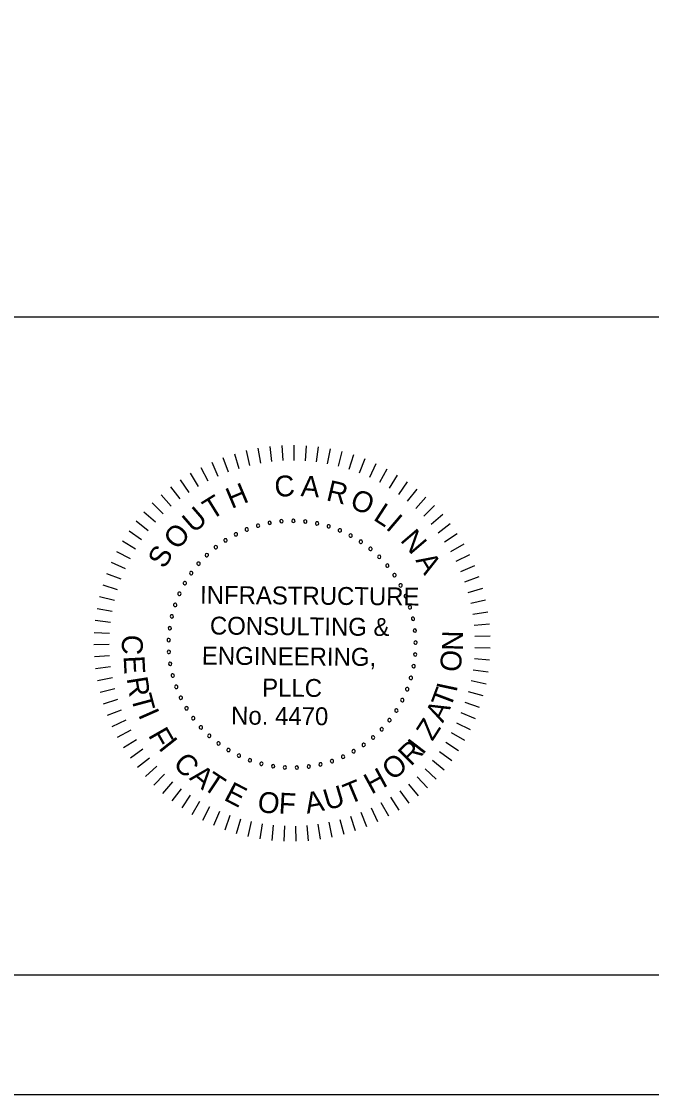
# Model space of a CAD drawing. Extents: x -144.4 to -96.3, y -117.1 to -87.8.
# Drawn here: x -110.83 to -107.33, y -117.06 to -111.1 of the extents above; entities that cross this region are included whole.
import ezdxf

# ---------------------------------------------------------------- set-up
doc = ezdxf.new("R2010")
doc.units = 0
for name, color, linetype in [('BR_BORDER LINES', 7, 'Continuous'), ('BR_TEXT', 7, 'Continuous'), ('Level 31', 7, 'Continuous')]:
    doc.layers.add(name, color=color, linetype=linetype)

msp = doc.modelspace()

# ---------------------------------------------------------------- linework, layer by layer
at = {"layer": 'BR_BORDER LINES'}
for p, q in [((-114.2473, -112.7399), (-107.1116, -112.7399)), ((-141.9121, -116.3976), (-97.1362, -116.3976))]:
    msp.add_line(p, q, dxfattribs=at)
at = {"layer": 'BR_TEXT'}
for p, q in [((-109.5838, -113.4838), (-109.564, -113.5661)), ((-109.518, -113.4702), (-109.5033, -113.5536)), ((-109.4516, -113.4606), (-109.442, -113.5448)), ((-109.3847, -113.4551), (-109.3802, -113.5397)), ((-109.3175, -113.4537), (-109.3182, -113.5384)), ((-109.2505, -113.4564), (-109.2563, -113.5409)), ((-109.1836, -113.4632), (-109.1946, -113.5471)), ((-109.1174, -113.474), (-109.1335, -113.5571)), ((-109.7122, -113.5229), (-109.6825, -113.6022)), ((-109.6486, -113.5014), (-109.6238, -113.5824)), ((-109.0519, -113.4888), (-109.073, -113.5708)), ((-108.9875, -113.5077), (-109.0135, -113.5882)), ((-108.9243, -113.5304), (-108.9552, -113.6092)), ((-109.8349, -113.5773), (-109.7958, -113.6524)), ((-109.7744, -113.5482), (-109.7399, -113.6256)), ((-108.8626, -113.5569), (-108.8983, -113.6337)), ((-108.8026, -113.5871), (-108.8429, -113.6616)), ((-109.9501, -113.6463), (-109.9021, -113.7161)), ((-109.8935, -113.61), (-109.8499, -113.6826)), ((-108.7446, -113.6209), (-108.7894, -113.6928)), ((-108.6888, -113.6582), (-108.7379, -113.7272)), ((-110.0043, -113.6859), (-109.9522, -113.7527)), ((-108.6353, -113.6989), (-108.6885, -113.7648)), ((-110.1049, -113.7747), (-110.0451, -113.8346)), ((-110.056, -113.7287), (-109.9999, -113.7922)), ((-108.5845, -113.7427), (-108.6416, -113.8052)), ((-110.151, -113.8235), (-110.0877, -113.8796)), ((-108.5364, -113.7895), (-108.5972, -113.8484)), ((-108.4912, -113.8392), (-108.5555, -113.8943)), ((-110.1941, -113.875), (-110.1274, -113.9272)), ((-108.4491, -113.8916), (-108.5167, -113.9426)), ((-110.2339, -113.9291), (-110.1642, -113.9771)), ((-108.4104, -113.9464), (-108.4809, -113.9932)), ((-110.2703, -113.9855), (-110.1978, -114.0292)), ((-108.375, -114.0034), (-108.4482, -114.0459)), ((-110.3033, -114.044), (-110.2282, -114.0832)), ((-108.3432, -114.0626), (-108.4189, -114.1005)), ((-110.3326, -114.1044), (-110.2553, -114.1389)), ((-108.315, -114.1235), (-108.3929, -114.1568)), ((-110.3582, -114.1665), (-110.2789, -114.1962)), ((-108.2906, -114.1861), (-108.3704, -114.2145)), ((-110.3799, -114.23), (-110.299, -114.2549)), ((-108.2701, -114.25), (-108.3514, -114.2735)), ((-110.3977, -114.2947), (-110.3154, -114.3146)), ((-108.2535, -114.3151), (-108.3361, -114.3336)), ((-110.4116, -114.3604), (-110.3282, -114.3753)), ((-108.2409, -114.381), (-108.3245, -114.3945)), ((-110.4214, -114.4269), (-110.3373, -114.4366)), ((-110.4271, -114.4938), (-110.3426, -114.4983)), ((-108.2323, -114.4476), (-108.3166, -114.4559)), ((-110.4288, -114.5609), (-110.3441, -114.5603)), ((-108.2279, -114.5146), (-108.3125, -114.5178)), ((-108.2275, -114.5817), (-108.3121, -114.5798)), ((-110.4264, -114.628), (-110.3419, -114.6222)), ((-108.2312, -114.6488), (-108.3155, -114.6416)), ((-110.4199, -114.6948), (-110.3359, -114.6839)), ((-108.239, -114.7155), (-108.3227, -114.7032)), ((-110.4093, -114.7611), (-110.3261, -114.7451)), ((-108.2508, -114.7816), (-108.3337, -114.7642)), ((-110.3947, -114.8266), (-110.3126, -114.8056)), ((-108.2666, -114.8468), (-108.3483, -114.8244)), ((-110.3761, -114.8912), (-110.2955, -114.8652)), ((-108.2864, -114.911), (-108.3666, -114.8836)), ((-110.3536, -114.9544), (-110.2748, -114.9236)), ((-108.3101, -114.9738), (-108.3884, -114.9416)), ((-110.3273, -115.0162), (-110.2505, -114.9806)), ((-110.2973, -115.0763), (-110.2228, -115.0361)), ((-108.3376, -115.0351), (-108.4138, -114.9982)), ((-110.2637, -115.1344), (-110.1918, -115.0897)), ((-108.3687, -115.0946), (-108.4425, -115.0531)), ((-110.2266, -115.1904), (-110.1576, -115.1414)), ((-108.4415, -115.2073), (-108.5098, -115.1572)), ((-108.4034, -115.152), (-108.4746, -115.1062)), ((-110.1862, -115.244), (-110.1202, -115.1909)), ((-108.483, -115.2601), (-108.5481, -115.2059)), ((-110.1426, -115.295), (-110.08, -115.238)), ((-108.5276, -115.3103), (-108.5892, -115.2523)), ((-110.0959, -115.3433), (-110.0369, -115.2825)), ((-110.0464, -115.3886), (-109.9912, -115.3244)), ((-108.5751, -115.3577), (-108.6331, -115.296)), ((-109.9942, -115.4309), (-109.943, -115.3634)), ((-108.6785, -115.4434), (-108.7285, -115.3751)), ((-108.6255, -115.4021), (-108.6796, -115.337)), ((-109.9395, -115.4699), (-109.8926, -115.3994)), ((-109.8826, -115.5055), (-109.84, -115.4323)), ((-108.7915, -115.5158), (-108.8329, -115.4419)), ((-108.7339, -115.4813), (-108.7797, -115.4101)), ((-109.8236, -115.5375), (-109.7856, -115.4618)), ((-109.7627, -115.5659), (-109.7294, -115.488)), ((-109.7003, -115.5905), (-109.6717, -115.5108)), ((-108.9125, -115.5739), (-108.9445, -115.4956)), ((-108.8511, -115.5467), (-108.8879, -115.4704)), ((-109.6364, -115.6113), (-109.6128, -115.53)), ((-109.5714, -115.6281), (-109.5528, -115.5455)), ((-109.5055, -115.641), (-109.492, -115.5574)), ((-109.439, -115.6498), (-109.4305, -115.5655)), ((-109.372, -115.6545), (-109.3687, -115.5699)), ((-109.3048, -115.6551), (-109.3067, -115.5705)), ((-109.2378, -115.6517), (-109.2448, -115.5673)), ((-109.1711, -115.6441), (-109.1832, -115.5603)), ((-109.1049, -115.6325), (-109.1222, -115.5496)), ((-109.0396, -115.6169), (-109.0619, -115.5352)), ((-108.9754, -115.5974), (-109.0026, -115.5172))]:
    msp.add_line(p, q, dxfattribs=at)
for centre, start, end in [((-109.5172, -113.9008), 16.14222, 196.14222), ((-109.5172, -113.9008), 196.14222, 16.14222), ((-109.4527, -113.8856), 10.60376, 190.60376), ((-109.4527, -113.8856), 190.60376, 10.60376), ((-109.387, -113.8767), 5.06529, 185.06529), ((-109.387, -113.8767), 185.06529, 5.06529), ((-109.3208, -113.8742), 359.52683, 179.52683), ((-109.3208, -113.8742), 179.52683, 359.52683), ((-109.2546, -113.8781), 353.98837, 173.98837), ((-109.2546, -113.8781), 173.98837, 353.98837), ((-109.1891, -113.8883), 168.44991, 348.44991), ((-109.1891, -113.8883), 348.44991, 168.44991), ((-109.125, -113.9048), 162.91145, 342.91145), ((-109.125, -113.9048), 342.91145, 162.91145), ((-109.6403, -113.9495), 27.21914, 207.21914), ((-109.6403, -113.9495), 207.21914, 27.21914), ((-109.5799, -113.9222), 21.68068, 201.68068), ((-109.5799, -113.9222), 201.68068, 21.68068), ((-109.0627, -113.9275), 157.37299, 337.37299), ((-109.0627, -113.9275), 337.37299, 157.37299), ((-109.0028, -113.956), 151.83453, 331.83453), ((-109.0028, -113.956), 331.83453, 151.83453), ((-109.7518, -114.0209), 38.29606, 218.29606), ((-109.7518, -114.0209), 218.29606, 38.29606), ((-109.6978, -113.9825), 32.7576, 212.7576), ((-109.6978, -113.9825), 212.7576, 32.7576), ((-108.9461, -113.9902), 146.29606, 326.29606), ((-108.9461, -113.9902), 326.29606, 146.29606), ((-108.8929, -114.0297), 140.7576, 320.7576), ((-108.8929, -114.0297), 320.7576, 140.7576), ((-109.8018, -114.0644), 43.83453, 223.83453), ((-109.8018, -114.0644), 223.83453, 43.83453), ((-108.8437, -114.0742), 135.21914, 315.21914), ((-108.8437, -114.0742), 315.21914, 135.21914), ((-109.8475, -114.1124), 49.37299, 229.37299), ((-109.8475, -114.1124), 229.37299, 49.37299), ((-108.7991, -114.1232), 129.68068, 309.68068), ((-108.7991, -114.1232), 309.68068, 129.68068), ((-109.8882, -114.1647), 54.91145, 234.91145), ((-109.8882, -114.1647), 234.91145, 54.91145), ((-108.7594, -114.1762), 124.14222, 304.14222), ((-108.7594, -114.1762), 304.14222, 124.14222), ((-109.9238, -114.2206), 60.44991, 240.44991), ((-109.9238, -114.2206), 240.44991, 60.44991), ((-108.725, -114.2329), 118.60376, 298.60376), ((-108.725, -114.2329), 298.60376, 118.60376), ((-109.9538, -114.2797), 65.98837, 245.98837), ((-109.9538, -114.2797), 245.98837, 65.98837), ((-108.6962, -114.2926), 113.06529, 293.06529), ((-108.6962, -114.2926), 293.06529, 113.06529), ((-109.9779, -114.3414), 71.52683, 251.52683), ((-109.9779, -114.3414), 251.52683, 71.52683), ((-108.6733, -114.3548), 107.52683, 287.52683), ((-108.6733, -114.3548), 287.52683, 107.52683), ((-109.996, -114.4052), 77.06529, 257.06529), ((-109.996, -114.4052), 257.06529, 77.06529), ((-108.6566, -114.4189), 101.98837, 281.98837), ((-108.6566, -114.4189), 281.98837, 101.98837), ((-110.0078, -114.4704), 82.60376, 262.60376), ((-110.0078, -114.4704), 262.60376, 82.60376), ((-108.6461, -114.4844), 96.44991, 276.44991), ((-108.6461, -114.4844), 276.44991, 96.44991), ((-110.0133, -114.5365), 88.14222, 268.14222), ((-110.0133, -114.5365), 268.14222, 88.14222), ((-108.642, -114.5505), 90.91145, 270.91145), ((-108.642, -114.5505), 270.91145, 90.91145), ((-110.0124, -114.6027), 93.68068, 273.68068), ((-110.0124, -114.6027), 273.68068, 93.68068), ((-108.6443, -114.6167), 85.37299, 265.37299), ((-108.6443, -114.6167), 265.37299, 85.37299), ((-110.005, -114.6686), 99.21914, 279.21914), ((-110.005, -114.6686), 279.21914, 99.21914), ((-108.6529, -114.6824), 79.83453, 259.83453), ((-108.6529, -114.6824), 259.83453, 79.83453), ((-109.9914, -114.7334), 104.7576, 284.7576), ((-109.9914, -114.7334), 284.7576, 104.7576), ((-108.6679, -114.747), 74.29606, 254.29606), ((-108.6679, -114.747), 254.29606, 74.29606), ((-109.9716, -114.7967), 110.29606, 290.29606), ((-109.9716, -114.7967), 290.29606, 110.29606), ((-109.9457, -114.8577), 115.83453, 295.83453), ((-109.9457, -114.8577), 295.83453, 115.83453), ((-108.689, -114.8098), 68.7576, 248.7576), ((-108.689, -114.8098), 248.7576, 68.7576), ((-109.9141, -114.916), 121.37299, 301.37299), ((-109.9141, -114.916), 301.37299, 121.37299), ((-108.7489, -114.9279), 57.68068, 237.68068), ((-108.7161, -114.8703), 63.21914, 243.21914), ((-108.7161, -114.8703), 243.21914, 63.21914), ((-109.877, -114.9709), 126.91145, 306.91145), ((-109.877, -114.9709), 306.91145, 126.91145), ((-108.7871, -114.9821), 52.14222, 232.14222), ((-108.7871, -114.9821), 232.14222, 52.14222), ((-108.7489, -114.9279), 237.68068, 57.68068), ((-109.8348, -115.022), 132.44991, 312.44991), ((-109.8348, -115.022), 312.44991, 132.44991), ((-108.8304, -115.0323), 46.60376, 226.60376), ((-108.8304, -115.0323), 226.60376, 46.60376), ((-109.7879, -115.0688), 137.98837, 317.98837), ((-109.7879, -115.0688), 317.98837, 137.98837), ((-108.8783, -115.0781), 41.06529, 221.06529), ((-108.8783, -115.0781), 221.06529, 41.06529), ((-109.7366, -115.1108), 143.52683, 323.52683), ((-109.7366, -115.1108), 323.52683, 143.52683), ((-109.6816, -115.1477), 149.06529, 329.06529), ((-109.6816, -115.1477), 329.06529, 149.06529), ((-108.9862, -115.1548), 29.98837, 209.98837), ((-108.9862, -115.1548), 209.98837, 29.98837), ((-108.9304, -115.119), 35.52683, 215.52683), ((-108.9304, -115.119), 215.52683, 35.52683), ((-109.6232, -115.1791), 154.60376, 334.60376), ((-109.6232, -115.1791), 334.60376, 154.60376), ((-109.5621, -115.2047), 160.14222, 340.14222), ((-109.5621, -115.2047), 340.14222, 160.14222), ((-109.4988, -115.2243), 345.68068, 165.68068), ((-109.1068, -115.2094), 18.91145, 198.91145), ((-109.1068, -115.2094), 198.91145, 18.91145), ((-109.0452, -115.185), 24.44991, 204.44991), ((-109.0452, -115.185), 204.44991, 24.44991), ((-109.4988, -115.2243), 165.68068, 345.68068), ((-109.4338, -115.2377), 171.21914, 351.21914), ((-109.4338, -115.2377), 351.21914, 171.21914), ((-109.368, -115.2448), 356.7576, 176.7576), ((-109.368, -115.2448), 176.7576, 356.7576), ((-109.3017, -115.2454), 2.29606, 182.29606), ((-109.3017, -115.2454), 182.29606, 2.29606), ((-109.2357, -115.2397), 7.83453, 187.83453), ((-109.2357, -115.2397), 187.83453, 7.83453), ((-109.1705, -115.2277), 13.37299, 193.37299), ((-109.1705, -115.2277), 193.37299, 13.37299)]:
    msp.add_arc(centre, 0.00932, start, end, dxfattribs=at)
at = {"layer": 'Level 31'}
msp.add_lwpolyline([(-144.3504, -117.0625), (-96.4704, -117.0625), (-96.4704, -87.8025), (-144.3504, -87.8025)], close=True, dxfattribs=at)

# ---------------------------------------------------------------- texts
at = {"layer": 'BR_TEXT'}
for s, height, rotation, p in [('H', 0.116, 22.78817, (-109.6644, -113.8088)), ('C', 0.116, 4.72812, (-109.4212, -113.7431)), ('A', 0.116, 355.69809, (-109.2823, -113.7365)), ('R', 0.116, 346.66807, (-109.1436, -113.7591)), ('T', 0.116, 31.81819, (-109.7772, -113.8722)), ('O', 0.116, 337.63804, (-109.0136, -113.7988)), ('L', 0.116, 327.10802, (-108.8821, -113.8659)), ('U', 0.116, 40.84822, (-109.8747, -113.9468)), ('I', 0.116, 319.578, (-108.8122, -113.9162)), ('O', 0.116, 49.87824, (-109.9638, -114.0413)), ('N', 0.116, 310.54797, (-108.7313, -113.9837)), ('S', 0.116, 58.90827, (-110.0375, -114.1453)), ('A', 0.116, 301.51795, (-108.6448, -114.0933)), ('INFRASTRUCTURE', 0.099446, 359.52683, (-109.8398, -114.3348)), ('CONSULTING &', 0.099446, 359.52683, (-109.7849, -114.5059)), ('N', 0.116, 89.20849, (-108.3797, -114.597)), ('C', 0.116, 267.02504, (-110.2702, -114.5043)), ('ENGINEERING,', 0.099446, 359.52683, (-109.8296, -114.6727)), ('O', 0.116, 83.20849, (-108.3945, -114.7187)), ('E', 0.116, 273.02504, (-110.2644, -114.6261)), ('R', 0.116, 279.02504, (-110.2474, -114.7488)), ('PLLC', 0.09945, 359.52683, (-109.4948, -114.8503)), ('T', 0.116, 69.39539, (-108.4493, -114.9205)), ('I', 0.116, 77.90926, (-108.4151, -114.8308)), ('T', 0.116, 285.02504, (-110.2243, -114.8536)), ('I', 0.116, 293.77127, (-110.1848, -114.9508)), ('No. 4470', 0.09945, 359.52683, (-109.6671, -115.0058)), ('A', 0.116, 63.39539, (-108.4902, -115.0008)), ('Z', 0.116, 57.39539, (-108.5485, -115.1023)), ('F', 0.116, 299.77127, (-110.13, -115.0653)), ('I', 0.116, 308.52683, (-110.074, -115.1369)), ('I', 0.116, 52.33388, (-108.6032, -115.179)), ('R', 0.116, 44.52683, (-108.6688, -115.2419)), ('C', 0.116, 314.52683, (-109.995, -115.2301)), ('O', 0.116, 38.52683, (-108.7707, -115.3217)), ('A', 0.116, 320.52683, (-109.9031, -115.3081)), ('T', 0.116, 326.52683, (-109.8306, -115.3592)), ('H', 0.116, 28.52683, (-108.8879, -115.3962)), ('E', 0.116, 332.52683, (-109.7129, -115.4228)), ('T', 0.116, 22.52683, (-109.0118, -115.4517)), ('O', 0.116, 350.52683, (-109.5265, -115.4878)), ('F', 0.116, 356.52683, (-109.4048, -115.4999)), ('A', 0.116, 10.52683, (-109.2454, -115.5021)), ('U', 0.116, 16.52683, (-109.1338, -115.4842))]:
    msp.add_text(s, height=height, rotation=rotation, dxfattribs=at).set_placement(p)

doc.saveas('drawing.dxf')
